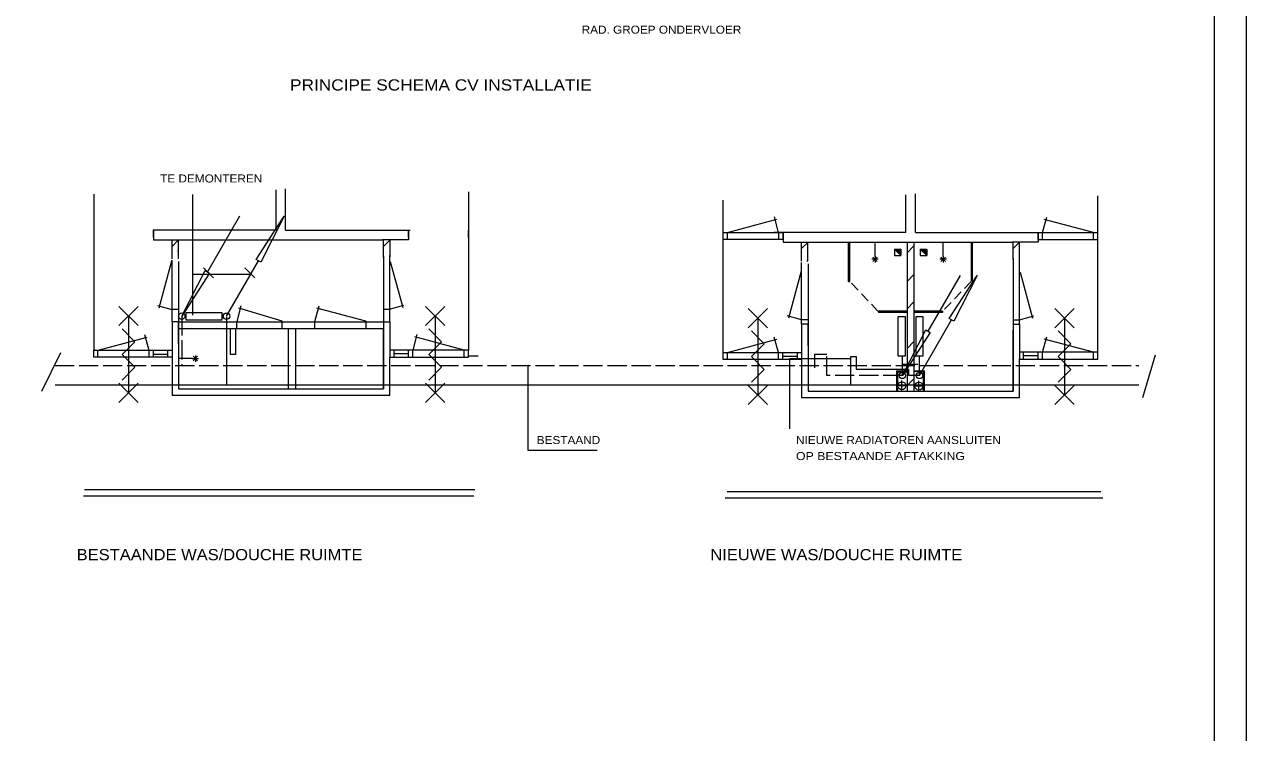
# Model space of a CAD drawing. Extents: x 295824 to 414724, y 24924 to 109024.
# Drawn here: x 376562 to 414724, y 61673 to 83782 of the extents above; entities that cross this region are included whole.
import ezdxf

# ---------------------------------------------------------------- set-up
doc = ezdxf.new("R2010")
doc.units = 0
doc.header["$LTSCALE"] = 100
for name, pattern in [('DOT_DASHED', [7.7, 5, -1.2, 0.3, -1.2]), ('LONG_DASHED', [7.5, 6, -1.5]), ('MEDIUM_DASHED', [4.5, 3, -1.5])]:
    doc.linetypes.add(name, pattern=pattern)
doc.layers.add('1', color=7, linetype='Continuous', lineweight=13)
doc.layers.add('16', color=7, linetype='Continuous', lineweight=13)

msp = doc.modelspace()

# ---------------------------------------------------------------- hatches: boundary and pattern name
at = {"layer": '1'}
for points in [[(403928.9, 76568.2), (403728.9, 76768.2), (403928.9, 76768.2)], [(404735, 76568.2), (404535, 76768.2), (404735, 76768.2)]]:
    msp.add_hatch(color=256, dxfattribs=at).paths.add_polyline_path(points)

# ---------------------------------------------------------------- linework, layer by layer
for p, q in [((414723.6, 24923.8), (414723.6, 109023.8)), ((384426.5, 77353.6), (384426.5, 78613.2)), ((384711.2, 77353.6), (384711.2, 78646.6)), ((378730.3, 78487.9), (378726.9, 73609.1)), ((381823.2, 74706.2), (381823.2, 78472.8)), ((390425.2, 78554.9), (390425.2, 73616.8)), ((398381.3, 73542.4), (398384.6, 78296.5)), ((404080.9, 77286.9), (404080.9, 78463.2)), ((404380.8, 77286.9), (404380.8, 78496.6)), ((410079.6, 73550.1), (410079.6, 78432)), ((398520.7, 77289.6), (400055.3, 77700.8)), ((400109.9, 77285.3), (399979.8, 77770.7)), ((408353.5, 77281.3), (408483.6, 77766.7)), ((409942.6, 77285.6), (408408, 77696.8)), ((384426.5, 77353.6), (380582.1, 77353.6)), ((380595.2, 77135.9), (380595.2, 77355.9)), ((384711.2, 77353.6), (388543.8, 77353.6)), ((384726.4, 77353.6), (388611.3, 77353.6)), ((388559.4, 77131.9), (388559.4, 77351.9)), ((390425.2, 77132.6), (390425.2, 77353.4)), ((398515.6, 77069.2), (398515.6, 77289.2)), ((404080.9, 77286.9), (399960.9, 77286.9)), ((400115.6, 77069.2), (400115.6, 77289.2)), ((400249.6, 77069.2), (400249.6, 77289.3)), ((404380.8, 77286.9), (408265.7, 77286.9)), ((404380.9, 77286.9), (410079.5, 77286.9)), ((408213.8, 77065.3), (408213.8, 77285.3)), ((408347.8, 77065.3), (408347.8, 77285.3)), ((409947.8, 77065.3), (409947.8, 77285.3)), ((410079.6, 77066), (410079.6, 77286.7)), ((380597, 77053.6), (387777.3, 77053.6)), ((381176.5, 76459.9), (381176.5, 77053.6)), ((381176.6, 76852.1), (381377.5, 77053)), ((381345.5, 76698.3), (381374.7, 76727.5)), ((381374, 76465.4), (381374, 77053.6)), ((387777.3, 76505.7), (387777.3, 77054.3)), ((387777.6, 76852.1), (387978.5, 77053)), ((387976.9, 76522.4), (387976.9, 77053.6)), ((400245.3, 77070), (398383.8, 77070)), ((400251.4, 76986.9), (407431.7, 76986.9)), ((400830.9, 76393.2), (400830.9, 76986.9)), ((400831, 76785.5), (401031.8, 76986.3)), ((401028.4, 76398.8), (401028.4, 76986.9)), ((402296.3, 75760.3), (402296.3, 76977.1)), ((402332.3, 75760.3), (402332.3, 76977.1)), ((403122.1, 76549.4), (403122.1, 76949.4)), ((404130.8, 76986.9), (404130.8, 75749.5)), ((404131.7, 76657.1), (404328.7, 76854.1)), ((404330.8, 76986.9), (404330.8, 76510)), ((405251, 76549.4), (405251, 76949.4)), ((406131.9, 75772.6), (406131.9, 76982.2)), ((406167.9, 75772.6), (406167.9, 76982.2)), ((407431.7, 76439.1), (407431.7, 76987.6)), ((407432, 76785.5), (407632.8, 76986.3)), ((407631.2, 76455.7), (407631.2, 76986.9)), ((408218, 77066), (410079.6, 77066)), ((381156.5, 76395.1), (380762.8, 74926)), ((381176.1, 74493.6), (381176.1, 76419)), ((381376.1, 76375.5), (381376.1, 74493.6)), ((387776.4, 76549.5), (387776.4, 74492.9)), ((387976.6, 75694.6), (387976.6, 76571.2)), ((387986.9, 76383), (388373, 74941.9)), ((400830.5, 74426.9), (400830.5, 76352.3)), ((400999.8, 76381.6), (401029, 76410.8)), ((403222.1, 76449.4), (403022.1, 76449.4)), ((403192.8, 76520.1), (403051.4, 76378.7)), ((403192.8, 76378.7), (403051.4, 76520.1)), ((403122.1, 76549.4), (403122.1, 76349.4)), ((404330.8, 76563.9), (404330.8, 72336.9)), ((405351, 76449.4), (405151, 76449.4)), ((405321.7, 76520.1), (405180.3, 76378.7)), ((405321.7, 76378.7), (405180.3, 76520.1)), ((405251, 76549.4), (405251, 76349.4)), ((407430.8, 76482.8), (407430.8, 74426.2)), ((407631, 75627.9), (407631, 76504.5)), ((400810.9, 76078.5), (400417.2, 74609.3)), ((401030.5, 76308.8), (401030.5, 74426.9)), ((404131.7, 75762), (404328.7, 75959)), ((407657.9, 76049.7), (408044.1, 74608.6)), ((387976.4, 74491.2), (387976.4, 75787)), ((402296.3, 75760.3), (402332.3, 75760.3)), ((404130.8, 75913.9), (404130.8, 72336.9)), ((406131.9, 75772.6), (406167.9, 75772.6)), ((407630.8, 74424.6), (407630.8, 75720.4)), ((379510.2, 74377.3), (380110.2, 74977.3)), ((380110.2, 74377.3), (379510.2, 74977.3)), ((381176.7, 74875.5), (380722, 74997.4)), ((381375.9, 74877.6), (381177.2, 74877.6)), ((383202.5, 74511.3), (383332.6, 74996.8)), ((384608.5, 74515.7), (383257.1, 74926.9)), ((385634.4, 74511.3), (385764.4, 74996.8)), ((387223.5, 74515.7), (385688.9, 74926.9)), ((387760, 74893.5), (387958.7, 74893.5)), ((387959.2, 74891.5), (388413.8, 75013.3)), ((389085.6, 74377.3), (389685.6, 74977.3)), ((389685.6, 74377.3), (389085.6, 74977.3)), ((399164.6, 74310.6), (399764.6, 74910.6)), ((399764.6, 74310.6), (399164.6, 74910.6)), ((404131.7, 74916.9), (404328.7, 75113.8)), ((405232.9, 74824.6), (404332.7, 74824.6)), ((405232.9, 74824.6), (405232.9, 74788.6)), ((408740, 74310.6), (409340, 74910.6)), ((409340, 74310.6), (408740, 74910.6)), ((379810.2, 74677.3), (379810.2, 72277.3)), ((381376.1, 74493.6), (381176.1, 74493.6)), ((381176.4, 74488.5), (381176.4, 72914.2)), ((381376.4, 73814.2), (381376.4, 74488.5)), ((381381.7, 74492.5), (387776.4, 74492.5)), ((382872.5, 74656.2), (382872.5, 72513.4)), ((383196.8, 74295.3), (383196.8, 74515.3)), ((384613.6, 74295.3), (384613.6, 74515.3)), ((385628.7, 74295.3), (385628.7, 74515.3)), ((387228.7, 74295.3), (387228.7, 74515.3)), ((387776.4, 74492.9), (387976.4, 74492.9)), ((387976.4, 74492.9), (387976.4, 73603.6)), ((389385.6, 74677.3), (389385.6, 72277.3)), ((399464.6, 74610.6), (399464.6, 72210.6)), ((400831, 74558.9), (400376.4, 74680.7)), ((401030.5, 74426.9), (400830.5, 74426.9)), ((400830.8, 74421.8), (400830.8, 72847.5)), ((401030.3, 74560.9), (400831.6, 74560.9)), ((401030.8, 73747.5), (401030.8, 74421.8)), ((404130.1, 74788.6), (403229.4, 74788.6)), ((405232.9, 74788.6), (404332.7, 74788.6)), ((407430.8, 74426.2), (407630.8, 74426.2)), ((407431, 74560.2), (407629.7, 74560.2)), ((407630.2, 74558.1), (408084.9, 74680)), ((407630.8, 74426.2), (407630.8, 73536.9)), ((409040, 74610.6), (409040, 72210.6)), ((380453, 73603.6), (380323, 74089.1)), ((381381.7, 74292.5), (387776.4, 74292.5)), ((384797.3, 74292.5), (384797.3, 72384)), ((385030.5, 74292.5), (385030.5, 72384)), ((388699.1, 73611.4), (388829.2, 74096.8)), ((378863.9, 73608), (380398.5, 74019.2)), ((390288.2, 73615.7), (388753.7, 74026.9)), ((398518.3, 73541.3), (400052.9, 73952.5)), ((400107.4, 73536.9), (399977.4, 74022.4)), ((404131.7, 73677), (404328.7, 73874)), ((408353.5, 73544.7), (408483.6, 74030.2)), ((409942.6, 73549), (408408, 73960.2)), ((378858.7, 73387.6), (378858.7, 73607.6)), ((380458.7, 73387.6), (380458.7, 73607.6)), ((380592.7, 73387.6), (380592.7, 73607.6)), ((380594.4, 73489.2), (381043.7, 73489.2)), ((381043.7, 73387.6), (381043.7, 73607.6)), ((381176.4, 73403.6), (381176.4, 72203.6)), ((381799.4, 73349.9), (381399.4, 73349.9)), ((381799.4, 73349.9), (381999.4, 73349.9)), ((381828.6, 73420.7), (381970.1, 73279.2)), ((381970.1, 73420.7), (381828.6, 73279.2)), ((381899.4, 73449.9), (381899.4, 73249.9)), ((387976.4, 72203.6), (387976.4, 73403.6)), ((388108.4, 73395.4), (388108.4, 73615.4)), ((388557.8, 73496.9), (388108.4, 73496.9)), ((388559.4, 73395.4), (388559.4, 73615.4)), ((388693.4, 73395.4), (388693.4, 73615.4)), ((390293.4, 73395.4), (390293.4, 73615.4)), ((390425.2, 73432.5), (390725.2, 73432.5)), ((398513.1, 73320.9), (398513.1, 73540.9)), ((400113.1, 73320.9), (400113.1, 73540.9)), ((400247.1, 73320.9), (400247.1, 73540.9)), ((400248.7, 73422.5), (400698.1, 73422.5)), ((400698.1, 73320.9), (400698.1, 73540.9)), ((400830.8, 73336.9), (400830.8, 72136.9)), ((402360.3, 73401.9), (402360.3, 72513.4)), ((407630.8, 72136.9), (407630.8, 73336.9)), ((407762.8, 73328.7), (407762.8, 73548.7)), ((408212.2, 73430.2), (407762.8, 73430.2)), ((408213.8, 73328.7), (408213.8, 73548.7)), ((408347.8, 73328.7), (408347.8, 73548.7)), ((409947.8, 73328.7), (409947.8, 73548.7)), ((403794.2, 72968.9), (404129.8, 72968.9)), ((403794.2, 72968.9), (403794.2, 72341.5)), ((403824.2, 72938.9), (404132.1, 72938.9)), ((403824.2, 72938.9), (403824.2, 72340.9)), ((404332.1, 72971.7), (404670.4, 72971.7)), ((404640.6, 72941.4), (404333.9, 72941.4)), ((404640.6, 72338.1), (404640.6, 72941.4)), ((404670.4, 72336.9), (404670.4, 72971.7)), ((377517.4, 72530.1), (411354.8, 72530.1)), ((379510.2, 71977.3), (380110.2, 72577.3)), ((380110.2, 71977.3), (379510.2, 72577.3)), ((389085.6, 71977.3), (389685.6, 72577.3)), ((389685.6, 71977.3), (389085.6, 72577.3)), ((399164.6, 71910.6), (399764.6, 72510.6)), ((399764.6, 71910.6), (399164.6, 72510.6)), ((404134.5, 72521), (404329.1, 72715.5)), ((408740, 71910.6), (409340, 72510.6)), ((409340, 71910.6), (408740, 72510.6)), ((381176.4, 72203.6), (385126.5, 72203.6)), ((384644.5, 72203.6), (387976.4, 72203.6)), ((384726, 72403.6), (385104.2, 72403.6)), ((384753.2, 72403.6), (387776.4, 72403.6)), ((400830.8, 72136.9), (404780.8, 72136.9)), ((404298.9, 72136.9), (407630.8, 72136.9)), ((404380.4, 72336.9), (404758.6, 72336.9)), ((404407.6, 72336.9), (407430.8, 72336.9)), ((390627, 69255.8), (378434.6, 69255.8)), ((410171.7, 69189.1), (398504.3, 69189.1)), ((384425.7, 69055.8), (378401.3, 69055.8)), ((390593.7, 69055.8), (384015.3, 69055.8)), ((404080, 68989.1), (398437.7, 68989.1)), ((410231.7, 68989.1), (403669.7, 68989.1))]:
    msp.add_line(p, q, dxfattribs=at)
at = {"layer": '1', "linetype": 'MEDIUM_DASHED'}
for p, q in [((403214.7, 74830.7), (402330.9, 75760.7)), ((406123.2, 75757.3), (405235.2, 74822.7))]:
    msp.add_line(p, q, dxfattribs=at)
at = {"layer": '1', "linetype": 'LONG_DASHED'}
for p, q in [((381473.4, 74672.9), (381473.4, 73130.1)), ((401227.7, 73476.9), (401227.7, 73063.4)), ((377517.4, 73130.1), (411354.8, 73130.1))]:
    msp.add_line(p, q, dxfattribs=at)
at = {"layer": '1', "linetype": 'DOT_DASHED'}
for p, q in [((403962.1, 72340.8), (403962.1, 72668.9)), ((404489.7, 72339.8), (404489.7, 72658.5)), ((404140.4, 72503.2), (403812.3, 72503.2)), ((404659.9, 72488.3), (404331.8, 72488.3)), ((404660.2, 72488.3), (404332.1, 72488.3))]:
    msp.add_line(p, q, dxfattribs=at)
at = {"layer": '1'}
for points in [[(304995.6, 25923.8), (413723.6, 25923.8), (413723.6, 108023.8), (304995.6, 108023.8)], [(384426.4, 77353.6), (380597, 77353.6), (380597, 77053.6)], [(388558.5, 77353.4), (388558.5, 77053.6), (387747.7, 77053.6)], [(398383.8, 77070), (398383.8, 77290.7), (400250.5, 77290.7)], [(404080.8, 77286.9), (400251.4, 77286.9), (400251.4, 76986.9)], [(408212.9, 77286.7), (408212.9, 76986.9), (407402.1, 76986.9)], [(403728.9, 76768.2), (403928.9, 76768.2), (403928.9, 76568.2)], [(404535, 76768.2), (404735, 76768.2), (404735, 76568.2)], [(381376.4, 74855.2), (381376.4, 72403.6), (385136.4, 72403.6)], [(404130.1, 74824.6), (403229.4, 74824.6), (403229.4, 74788.6)], [(387776.4, 74492.9), (387776.4, 72403.6), (387776.4, 74303.6)], [(401030.8, 74788.6), (401030.8, 72336.9), (404790.8, 72336.9)], [(407430.8, 74426.2), (407430.8, 72336.9), (407430.8, 74236.9)], [(379610.2, 74277.3), (380010.2, 73877.3), (379610.2, 73477.3), (380010.2, 73077.3), (379610.2, 72677.3)], [(383148.4, 74275.6), (383148.4, 73475.6), (382998.4, 73475.6), (382998.4, 74275.6)], [(389185.6, 74277.3), (389585.6, 73877.3), (389185.6, 73477.3), (389585.6, 73077.3), (389185.6, 72677.3)], [(399264.6, 74210.6), (399664.6, 73810.6), (399264.6, 73410.6), (399664.6, 73010.6), (399264.6, 72610.6)], [(408840, 74210.6), (409240, 73810.6), (408840, 73410.6), (409240, 73010.6), (408840, 72610.6)], [(392283.3, 73156.2), (392283.3, 70489.6), (394448.6, 70489.6)]]:
    msp.add_lwpolyline(points, dxfattribs=at)
for points in [[(403728.9, 76768.2), (403728.9, 76568.2), (403928.9, 76568.2)], [(403928.9, 76568.2), (403728.9, 76768.2), (403928.9, 76768.2)], [(404535, 76768.2), (404535, 76568.2), (404735, 76568.2)], [(404735, 76568.2), (404535, 76768.2), (404735, 76768.2)], [(381606.6, 74556.2), (382739.2, 74556.2), (382739.2, 74772.8), (381606.6, 74772.8)], [(378726.9, 73388.3), (378726.9, 73609.1), (381175.5, 73609.1), (381175.5, 73388.3)], [(390425.2, 73396.1), (390425.2, 73616.8), (387976.6, 73616.8), (387976.6, 73396.1)], [(398381.3, 73321.6), (398381.3, 73542.4), (400829.9, 73542.4), (400829.9, 73321.6)], [(410079.6, 73329.4), (410079.6, 73550.1), (407631, 73550.1), (407631, 73329.4)]]:
    msp.add_lwpolyline(points, close=True, dxfattribs=at)
for centre in [(403962.1, 72501.4), (404491.1, 72489.7)]:
    msp.add_circle(centre, 125, dxfattribs=at)
at = {"layer": '16'}
for p, q in [((383273.4, 77790.9), (382273.4, 76058.9)), ((382872.5, 74672.8), (383872.5, 76404.8)), ((383655.5, 75970.2), (381823.2, 75970.2)), ((382154.9, 76184.7), (382464.7, 75874.9)), ((383441.2, 76184.7), (383750.9, 75874.9)), ((405776, 75940.9), (404776, 74208.9)), ((404509, 72822.9), (405509, 74554.9)), ((377692.9, 73523.6), (377093.3, 72323.6)), ((404509, 72822.9), (404509, 73418.5)), ((411871.5, 73456.9), (411471.8, 72123.7))]:
    msp.add_line(p, q, dxfattribs=at)
at = {"layer": '16', "linetype": 'LONG_DASHED'}
for p, q in [((403976, 72822.9), (403976, 73435.2)), ((403979, 73176.9), (404453.7, 73176.9))]:
    msp.add_line(p, q, dxfattribs=at)
at = {"layer": '16'}
for points in [[(384672.5, 77790.8), (383944.5, 76362.8), (383800.5, 76446.8)], [(381473.4, 74672.9), (382201.4, 76100.9), (382345.4, 76016.9)], [(406309, 75940.9), (405581, 74512.9), (405437, 74596.9)], [(403837.1, 73439), (404070.3, 73439), (404070.3, 74655.6), (403837.1, 74655.6)], [(404395.1, 73439), (404628.3, 73439), (404628.3, 74655.6), (404395.1, 74655.6)], [(403976, 72822.9), (404704, 74250.9), (404848, 74166.9)]]:
    msp.add_lwpolyline(points, close=True, dxfattribs=at)
for points in [[(402353.5, 73341.1), (400454.7, 73341.1), (400454.7, 71157.8)], [(404509, 72822.9), (404178.9, 72822.9), (404178.9, 73010.2), (402546.6, 73010.2), (402546.6, 73401.9), (402360.3, 73401.9)]]:
    msp.add_lwpolyline(points, dxfattribs=at)
at = {"layer": '16', "linetype": 'LONG_DASHED'}
msp.add_lwpolyline([(403976, 72822.9), (401613.8, 72822.9), (401613.8, 73476.9), (401227.7, 73476.9)], dxfattribs=at)
at = {"layer": '16'}
for centre in [(381473.4, 74673.5), (382872.5, 74672.2), (403976, 72823.5), (404509, 72822.3)]:
    msp.add_circle(centre, 100, dxfattribs=at)

# ---------------------------------------------------------------- texts
for s, height, width, p in [('RAD. GROEP ONDERVLOER', 250, 1.1, (393960.9, 83494.4)), ('PRINCIPE SCHEMA CV INSTALLATIE', 350, 1.15, (384855.6, 81718.4)), ('TE DEMONTEREN', 250, 1.1, (380800.2, 78847.2)), ('BESTAAND ', 250, 1.1, (392559.5, 70680.7)), ('NIEUWE RADIATOREN AANSLUITEN ', 250, 1.1, (400654.5, 70680.7)), ('OP BESTAANDE AFTAKKING', 250, 1.15, (400654.5, 70180.7)), ('BESTAANDE WAS/DOUCHE RUIMTE', 350, 1.1, (378193.1, 67052)), ('NIEUWE WAS/DOUCHE RUIMTE', 350, 1.1, (397980.8, 67052))]:
    msp.add_text(s, height=height, dxfattribs=dict(at, width=width)).set_placement(p)

doc.saveas('drawing.dxf')
